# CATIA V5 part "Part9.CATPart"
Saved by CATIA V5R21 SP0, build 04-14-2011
Part number: Part1
Bounding box of the stored display mesh (mm): x 0 to 0, y -40 to 40, z -39.99 to 132
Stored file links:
  C:\Users\RIAD MAHAMUD PIASH\Desktop\Part9.CATPart
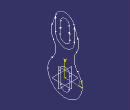
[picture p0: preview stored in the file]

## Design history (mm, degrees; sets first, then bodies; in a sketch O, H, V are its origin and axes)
Body1 (main body)
  Sketch1 on yz-plane, origin (0, 0, 0), H (0, 1, 0), V (0, 0, 1)
    arc A1 centre (0, 0) radius 40 from (40, 0) to (29.4135, 27.108) ccw
    arc A2 centre (0, 10) radius 12 from (11.9693, 9.1429) to (-11.9693, 9.1429) ccw
    point P1 (0, 10)
    arc A3 centre (0, -18) radius 10 from (-9.9745, -18.7143) to (9.9745, -18.7143) ccw
    point P2 (0, -18)
    point P3 (0, 82)
    line L1 (-11.9693, 9.1429) -> (-9.9745, -18.7143)
    point P4 (-9.9745, -18.7143)
    point P5 (-11.9693, 9.1429)
    point P6 (9.9745, -18.7143)
    point P7 (11.9693, 9.1429)
    line L2 (11.9693, 9.1429) -> (9.9745, -18.7143)
    construction line L3 (0, 82) -> (0, 110)
    point P8 (0, 110)
    construction line L4 (0, 82) -> (0, 110)
    line L5 (-22, 82) -> (-22, 110)
    line L6 (22, 110) -> (22, 82)
    arc A4 centre (0, 110) radius 22 from (-22, 110) to (22, 110) cw
    arc A5 centre (0, 82) radius 22 from (22, 82) to (-22, 82) cw
    construction line L7 (0, 82) -> (0, 110)
    line L8 (-12, 82) -> (-12, 94.257)
    line L9 (12, 94.257) -> (12, 82)
    arc A6 centre (0, 82) radius 12 from (12, 82) to (-12, 82) cw
    construction line L10 (0, 82) -> (0, 110)
    line L11 (-10, 96) -> (-10, 110)
    line L12 (10, 110) -> (10, 96)
    arc A7 centre (0, 110) radius 10 from (-10, 110) to (10, 110) cw
    line L13 (-10.257, 96) -> (-10, 96)
    line L14 (10, 96) -> (10.257, 96)
    arc A8 centre (-10.257, 94.257) radius 1.743 from (-12, 94.257) to (-10.257, 96) cw
    point P19 (-12, 94.257)
    point P20 (-10.257, 96)
    point P22 (10.257, 96)
    point P23 (12, 94.257)
    arc A9 centre (10.257, 94.257) radius 1.743 from (12, 94.257) to (10.257, 96) ccw
    line L15 (20.5491, 117.8571) -> (29.8896, 93.4286)
    point P25 (20.5491, 117.8571)
    point P26 (29.8896, 93.4286)
    point P27 (-29.8896, 93.4286)
    point P28 (-20.5491, 117.8571)
    line L16 (-20.5491, 117.8571) -> (-29.8896, 93.4286)
    arc A10 centre (0, 82) radius 32 from (26.5671, 64.1621) to (29.8896, 93.4286) ccw
    arc A11 centre (51.4737, 47.439) radius 30 from (26.5671, 64.1621) to (29.4135, 27.108) ccw
    point P29 (26.5671, 64.1621)
    point P30 (29.4135, 27.108)
    point P31 (40, 0)
    point P33 (-29.4135, 27.108)
    point P34 (-40, 0)
    arc A12 centre (0, 0) radius 40 from (-40, 0) to (-29.4135, 27.108) cw
    point P36 (-26.5671, 64.1621)
    arc A13 centre (-51.4737, 47.439) radius 30 from (-26.5671, 64.1621) to (-29.4135, 27.108) cw
    point P38 (-29.8896, 93.4286)
    arc A14 centre (0, 82) radius 32 from (-26.5671, 64.1621) to (-29.8896, 93.4286) cw
    arc A15 centre (0, 0) radius 40 from (-40, 0) to (40, 0) ccw
    arc A16 centre (0, 110) radius 22 from (20.5491, 117.8571) to (-20.5491, 117.8571) ccw
    point P40 (-20.5491, 117.8571)
    radius A1 = 40
    radius A2 = 12
    radius A3 = 10
    distance P1 H = 10
    distance P2 H = 18
    length L3 = 28
    distance L4 L5 = 22
    distance L7 L8 = 12
    distance L10 L11 = 10
    distance L13 P3 = 14
    distance P8 P2 = 128
    radius A8 = 1.743
    radius A11 = 30
    coincidence: P3 V, P1 V, P2 V, L13 L14, A4 P25, A10 P27, P40 L16
    tangency: L1 A2, A3 L1, A4 L5, A5 L5, A4 L6, A5 L6, A6 L8, A6 L9, A7 L11, A7 L12, A8 L8, A8 L13, L15 A4, A11 A10, A11 A1, A15 A11, A16 L16
    symmetry: P4 P6 V, P5 P7 V, L1 L2 V, P20 P22 L10, P19 P23 L10, A8 A9 L10, P26 P27 V, P25 P28 V, L15 L16 V, P30 P33 V, P31 P34 V, A1 A12 V, P29 P36 V, A11 A13 V, P26 P38 V, A10 A14 V
    vertical: L3 V, L4 V, L7 V, L10 V
    horizontal: L13 H, L14 H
